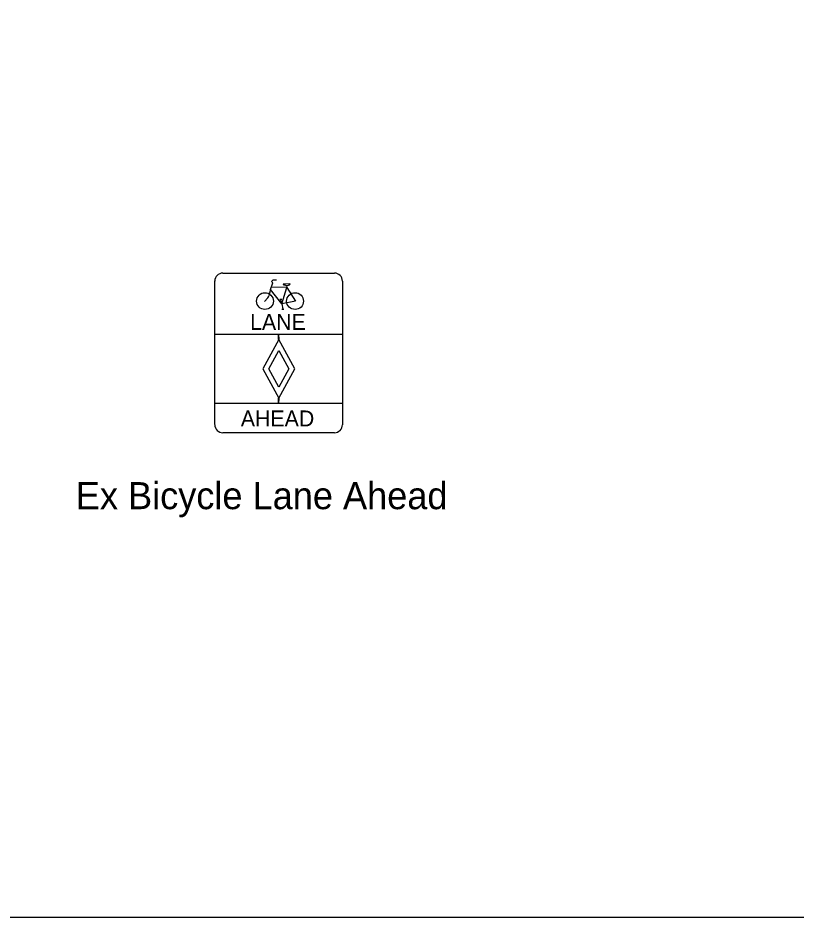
# Model space of a CAD drawing. Extents: x 42133 to 45533, y 41351 to 47951.
# Drawn here: x 42944.7 to 43160.6, y 46901.4 to 47150.7 of the extents above; entities that cross this region are included whole.
import ezdxf

# ---------------------------------------------------------------- set-up
doc = ezdxf.new("R2010")
doc.units = 0
doc.layers.add('P_ODOT_PLAN_Border', color=7, linetype='Continuous')
doc.layers.add('P_TRAF_SIGN_SignDetails', color=7, linetype='Continuous')

msp = doc.modelspace()

# ---------------------------------------------------------------- linework, layer by layer
at = {"layer": 'P_ODOT_PLAN_Border'}
msp.add_lwpolyline([(42208.34, 46901.35), (43808.34, 46901.35), (43808.34, 47901.35), (42208.34, 47901.35)], close=True, dxfattribs=at)
at = {"layer": 'P_TRAF_SIGN_SignDetails'}
for p, q in [((43001.57, 47079.96), (43032.56, 47079.96)), ((42999.36, 47037.95), (42999.36, 47077.8)), ((43014.86, 47075.44), (43015.43, 47077.28)), ((43014.86, 47075.44), (43015.43, 47077.28)), ((43019.34, 47076), (43015.04, 47076.02)), ((43019.34, 47076), (43015.04, 47076.02)), ((43015.13, 47077.62), (43015.55, 47078.04)), ((43015.13, 47077.62), (43015.55, 47078.04)), ((43015.43, 47077.28), (43015.13, 47077.62)), ((43015.43, 47077.28), (43015.13, 47077.62)), ((43015.55, 47078.04), (43016.48, 47078.11)), ((43015.55, 47078.04), (43016.48, 47078.11)), ((43017.94, 47071.44), (43019.34, 47076)), ((43017.94, 47071.44), (43019.34, 47076)), ((43020.22, 47077), (43018.33, 47076.9)), ((43020.22, 47077), (43018.33, 47076.9)), ((43019.34, 47076), (43019.48, 47076.54)), ((43019.34, 47076), (43019.48, 47076.54)), ((43019.34, 47076), (43021.72, 47072.17)), ((43019.34, 47076), (43021.72, 47072.17)), ((43034.78, 47077.75), (43034.78, 47037.9)), ((43014.86, 47075.44), (43014.37, 47073.67)), ((43014.86, 47075.44), (43014.37, 47073.67)), ((43017.94, 47071.44), (43014.86, 47075.44)), ((43017.94, 47071.44), (43014.86, 47075.44)), ((43014.11, 47073.09), (43013.18, 47072.07)), ((43014.11, 47073.09), (43013.18, 47072.07)), ((43017.4, 47072.69), (43017.94, 47072.69)), ((43017.4, 47072.69), (43017.94, 47072.69)), ((43017.94, 47071.44), (43017.71, 47072.66)), ((43017.94, 47071.44), (43017.71, 47072.66)), ((43021.72, 47072.17), (43017.94, 47071.44)), ((43021.72, 47072.17), (43017.94, 47071.44)), ((43017.94, 47071.44), (43018.23, 47069.96)), ((43017.94, 47071.44), (43018.23, 47069.96)), ((43017.95, 47069.97), (43018.49, 47069.97)), ((43017.95, 47069.97), (43018.49, 47069.97)), ((42999.34, 47062.98), (43017.08, 47062.98)), ((42999.34, 47043.8), (42999.34, 47062.98)), ((43017.09, 47061.52), (43012.68, 47053.39)), ((43017.05, 47062.98), (43017.05, 47061.52)), ((43017.05, 47061.52), (43017.05, 47062.98)), ((43017.08, 47062.98), (43017.09, 47061.52)), ((43017.08, 47062.98), (43034.75, 47062.98)), ((43021.53, 47053.39), (43017.09, 47061.52)), ((43034.75, 47062.98), (43034.75, 47043.8)), ((43014.37, 47053.38), (43017.12, 47058.46)), ((43017.12, 47058.46), (43019.89, 47053.39)), ((43012.68, 47053.39), (43017.09, 47045.27)), ((43017.12, 47048.32), (43014.37, 47053.38)), ((43017.09, 47045.27), (43021.53, 47053.39)), ((43019.89, 47053.39), (43017.12, 47048.32)), ((43017.05, 47043.8), (42999.34, 47043.8)), ((43017.05, 47045.27), (43017.05, 47043.8)), ((43017.09, 47045.27), (43017.05, 47043.8)), ((43017.05, 47043.8), (43017.05, 47045.27)), ((43034.75, 47043.8), (43017.05, 47043.8)), ((43032.56, 47035.69), (43001.57, 47035.69))]:
    msp.add_line(p, q, dxfattribs=at)
for centre in [(43013.28, 47072.19), (43013.28, 47072.19), (43021.63, 47072.19), (43021.63, 47072.19)]:
    msp.add_circle(centre, 2.33, dxfattribs=at)
for centre, radius, start, end in [((43001.57, 47077.74), 2.21, 90, 180), ((43032.56, 47077.74), 2.21, 360, 90), ((43018.37, 47076.85), 0.0547, 98.1714, 240.5811), ((43018.37, 47076.85), 0.0547, 98.1714, 240.5811), ((43019.71, 47079.96), 3.44, 246.229, 261.8057), ((43019.71, 47079.96), 3.44, 246.229, 261.8057), ((43019.45, 47077.5), 0.974, 256.4886, 325.1285), ((43019.45, 47077.5), 0.974, 256.4886, 325.1285), ((43020.2, 47076.96), 0.0475, 336.8194, 78.5167), ((43020.2, 47076.96), 0.0475, 336.8194, 78.5167), ((43002.73, 47078.53), 12.61, 334.4184, 337.3217), ((43002.73, 47078.53), 12.61, 334.4184, 337.3217), ((43001.57, 47037.9), 2.21, 180, 270), ((43032.56, 47037.9), 2.21, 270, 0)]:
    msp.add_arc(centre, radius, start, end, dxfattribs=at)

# ---------------------------------------------------------------- texts
for s, height, p in [('LANE', 4.425, (43009.15, 47064.19)), ('AHEAD', 4.425, (43006.57, 47037.42)), ('Ex Bicycle Lane Ahead', 7.5, (42960.79, 47014.47))]:
    msp.add_text(s, height=height, dxfattribs=at).set_placement(p)

doc.saveas('drawing.dxf')
